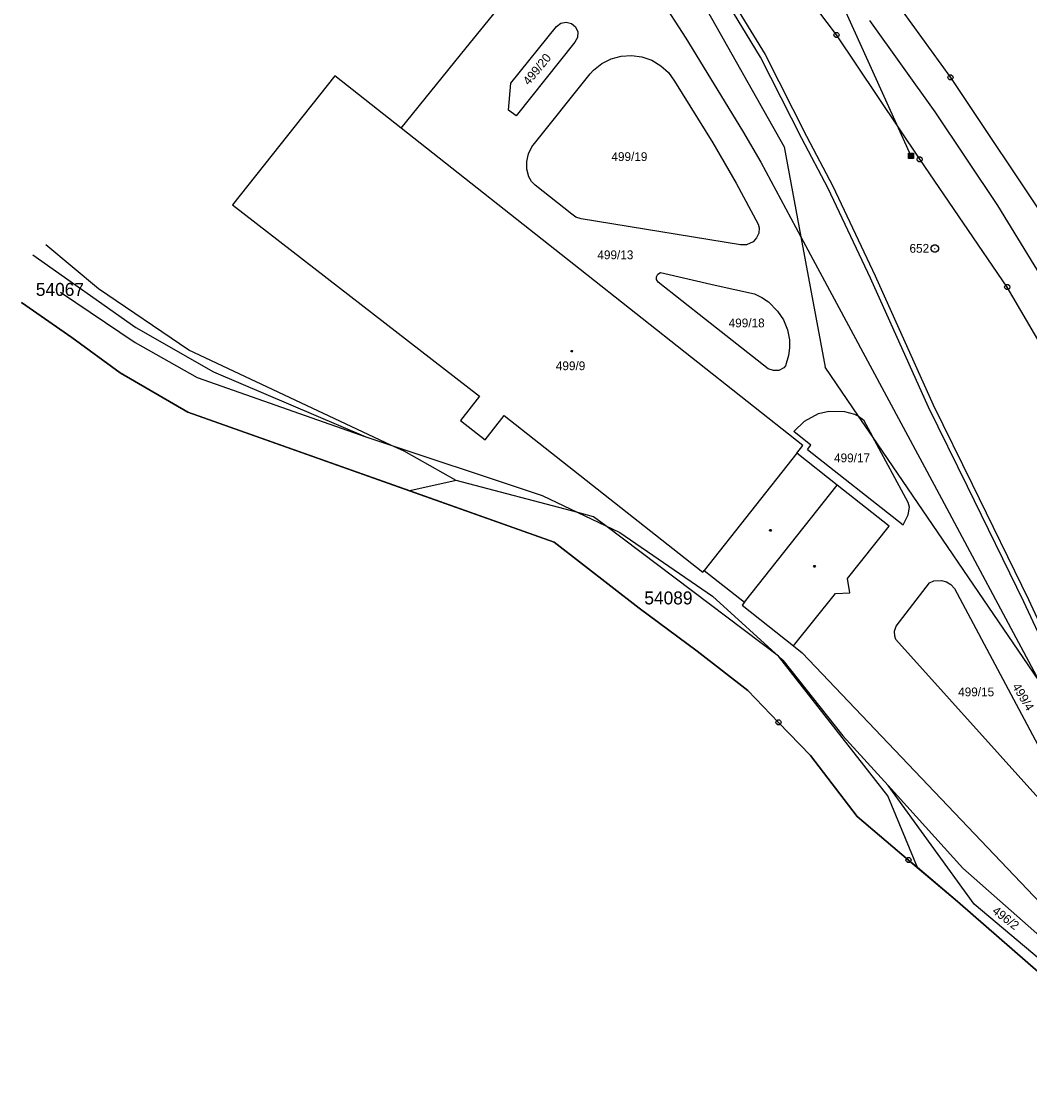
# Model space of a CAD drawing. Extents: x -755359 to -754474, y -1162585 to -1161655.
# Drawn here: x -755359.1 to -755164.4, y -1162482.8 to -1162276.2 of the extents above; entities that cross this region are included whole.
import ezdxf

# ---------------------------------------------------------------- set-up
doc = ezdxf.new("R2010")
doc.units = 0
for name, color, linetype in [('Vrstva 1', 7, 'Continuous'), ('Vrstva 11', 7, 'Continuous'), ('Vrstva 12', 7, 'Continuous'), ('Vrstva 13', 7, 'Continuous'), ('Vrstva 2', 7, 'Continuous'), ('Vrstva 4', 7, 'Continuous'), ('Vrstva 5', 7, 'Continuous'), ('Vrstva 6', 7, 'Continuous'), ('Vrstva 7', 7, 'Continuous'), ('Vrstva 8', 7, 'Continuous')]:
    doc.layers.add(name, color=color, linetype=linetype)

msp = doc.modelspace()

# ---------------------------------------------------------------- linework, layer by layer
at = {"layer": 'Vrstva 1'}
for p, q in [((-755201.65, -1162278.82), (-755218.86, -1162255.78)), ((-755197.95, -1162261.69), (-755179.66, -1162287.01)), ((-755273.15, -1162281.3), (-755259.96, -1162264.99)), ((-755228.92, -1162270), (-755211.8, -1162300.42)), ((-755236.16, -1162271.02), (-755230.79, -1162279.46)), ((-755255.71, -1162277.19), (-755254.89, -1162276.55)), ((-755254.89, -1162276.55), (-755253.87, -1162276.34)), ((-755253.87, -1162276.34), (-755252.85, -1162276.59)), ((-755252.85, -1162276.59), (-755252.05, -1162277.27)), ((-755264.53, -1162288.11), (-755255.71, -1162277.19)), ((-755252.05, -1162277.27), (-755251.62, -1162278.23)), ((-755251.62, -1162278.23), (-755251.7, -1162279.29)), ((-755252.21, -1162280.19), (-755263.5, -1162294.45)), ((-755251.7, -1162279.29), (-755252.21, -1162280.19)), ((-755230.79, -1162279.46), (-755219.8, -1162297.35)), ((-755185.6, -1162302.84), (-755201.65, -1162278.82)), ((-755285.72, -1162296.84), (-755273.15, -1162281.3)), ((-755245.19, -1162283.44), (-755243.24, -1162282.9)), ((-755243.24, -1162282.9), (-755241.22, -1162282.77)), ((-755241.22, -1162282.77), (-755239.23, -1162283.04)), ((-755248.56, -1162285.61), (-755246.99, -1162284.35)), ((-755246.99, -1162284.35), (-755245.19, -1162283.44)), ((-755239.23, -1162283.04), (-755237.32, -1162283.7)), ((-755237.32, -1162283.7), (-755235.58, -1162284.76)), ((-755235.58, -1162284.76), (-755234.1, -1162286.1)), ((-755298.53, -1162286.71), (-755318.27, -1162311.63)), ((-755285.72, -1162296.84), (-755298.53, -1162286.71)), ((-755260.47, -1162300.43), (-755249.26, -1162286.35)), ((-755249.26, -1162286.35), (-755248.56, -1162285.61)), ((-755234.1, -1162286.1), (-755232.92, -1162287.74)), ((-755179.66, -1162287.01), (-755159.89, -1162316.68)), ((-755265.01, -1162293.32), (-755264.53, -1162288.11)), ((-755232.92, -1162287.74), (-755225.57, -1162299.65)), ((-755263.5, -1162294.45), (-755265.01, -1162293.32)), ((-755251.18, -1162324.13), (-755285.72, -1162296.84)), ((-755219.8, -1162297.35), (-755216.28, -1162303.42)), ((-755261.16, -1162301.78), (-755260.47, -1162300.43)), ((-755225.57, -1162299.65), (-755221.06, -1162307.45)), ((-755211.8, -1162300.42), (-755208.54, -1162317.82)), ((-755261.48, -1162303.26), (-755261.16, -1162301.78)), ((-755261.47, -1162304.77), (-755261.48, -1162303.26)), ((-755216.28, -1162303.42), (-755208.54, -1162317.82)), ((-755168.69, -1162327.53), (-755185.6, -1162302.84)), ((-755261.1, -1162306.25), (-755261.47, -1162304.77)), ((-755260.58, -1162307.15), (-755261.1, -1162306.25)), ((-755259.87, -1162307.84), (-755260.58, -1162307.15)), ((-755221.06, -1162307.45), (-755216.79, -1162315.38)), ((-755252.8, -1162313.43), (-755259.87, -1162307.84)), ((-755318.27, -1162311.63), (-755270.6, -1162348.62)), ((-755251.97, -1162314.01), (-755252.8, -1162313.43)), ((-755250.99, -1162314.33), (-755251.97, -1162314.01)), ((-755220.22, -1162319.37), (-755250.99, -1162314.33)), ((-755216.79, -1162315.38), (-755216.6, -1162316.07)), ((-755217.09, -1162318.02), (-755217.77, -1162318.78)), ((-755216.69, -1162317.09), (-755217.09, -1162318.02)), ((-755216.6, -1162316.07), (-755216.69, -1162317.09)), ((-755208.54, -1162317.82), (-755203.83, -1162343)), ((-755219.05, -1162319.34), (-755220.22, -1162319.37)), ((-755217.77, -1162318.78), (-755219.05, -1162319.34)), ((-755356.88, -1162321.27), (-755356.88, -1162321.27)), ((-755356.88, -1162321.27), (-755336.95, -1162335.3)), ((-755208.16, -1162358.13), (-755251.18, -1162324.13)), ((-755236.45, -1162325.52), (-755236.16, -1162325.01)), ((-755236.44, -1162326.06), (-755236.45, -1162325.52)), ((-755236.12, -1162326.55), (-755236.44, -1162326.06)), ((-755236.16, -1162325.01), (-755235.64, -1162324.73)), ((-755235.64, -1162324.73), (-755225.07, -1162327.13)), ((-755226.97, -1162333.77), (-755236.12, -1162326.55)), ((-755225.07, -1162327.13), (-755217.5, -1162328.85)), ((-755155.26, -1162350.62), (-755168.69, -1162327.53)), ((-755351.54, -1162328.52), (-755351.54, -1162328.52)), ((-755351.54, -1162328.52), (-755337.08, -1162338.23)), ((-755217.5, -1162328.85), (-755216.09, -1162329.51)), ((-755216.09, -1162329.51), (-755214.81, -1162330.37)), ((-755214.81, -1162330.37), (-755213.06, -1162332.17)), ((-755359.06, -1162330.53), (-755359.06, -1162330.53)), ((-755359.06, -1162330.53), (-755349.35, -1162337.24)), ((-755213.06, -1162332.17), (-755211.93, -1162333.85)), ((-755214.89, -1162343.31), (-755226.97, -1162333.77)), ((-755211.93, -1162333.85), (-755211.16, -1162335.75)), ((-755336.95, -1162335.3), (-755321.94, -1162343.88)), ((-755211.16, -1162335.75), (-755210.72, -1162337.72)), ((-755349.35, -1162337.24), (-755339.99, -1162344.07)), ((-755337.08, -1162338.23), (-755325.14, -1162344.97)), ((-755210.72, -1162337.72), (-755210.71, -1162339.28)), ((-755210.71, -1162339.28), (-755210.94, -1162340.77)), ((-755211.5, -1162342.72), (-755211.86, -1162343.11)), ((-755210.94, -1162340.77), (-755211.5, -1162342.72)), ((-755339.99, -1162344.07), (-755326.91, -1162351.67)), ((-755321.94, -1162343.88), (-755292.52, -1162356.43)), ((-755213.83, -1162343.62), (-755214.89, -1162343.31)), ((-755212.81, -1162343.61), (-755213.83, -1162343.62)), ((-755211.86, -1162343.11), (-755212.81, -1162343.61)), ((-755197.4, -1162352.43), (-755203.83, -1162343)), ((-755325.14, -1162344.97), (-755292.52, -1162356.43)), ((-755270.6, -1162348.62), (-755274.29, -1162353.28)), ((-755326.91, -1162351.67), (-755256.17, -1162376.79)), ((-755269.5, -1162357.01), (-755265.84, -1162352.32)), ((-755265.84, -1162352.32), (-755227.45, -1162382.59)), ((-755207.82, -1162353.4), (-755205.14, -1162351.97)), ((-755205.14, -1162351.97), (-755203.16, -1162351.5)), ((-755203.16, -1162351.5), (-755200.13, -1162351.55)), ((-755200.13, -1162351.55), (-755198.17, -1162352.07)), ((-755198.17, -1162352.07), (-755197.4, -1162352.43)), ((-755194.7, -1162356.4), (-755197.4, -1162352.43)), ((-755274.29, -1162353.28), (-755269.5, -1162357.01)), ((-755209.93, -1162355.45), (-755207.82, -1162353.4)), ((-755292.52, -1162356.43), (-755258.5, -1162367.8)), ((-755206.63, -1162358.07), (-755209.93, -1162355.45)), ((-755187.86, -1162369.11), (-755194.7, -1162356.4)), ((-755162.59, -1162403.5), (-755194.7, -1162356.4)), ((-755209.34, -1162359.63), (-755208.16, -1162358.13)), ((-755207.28, -1162358.88), (-755206.63, -1162358.07)), ((-755207.28, -1162358.88), (-755188.78, -1162373.43)), ((-755201.54, -1162365.82), (-755209.34, -1162359.63)), ((-755191.47, -1162373.73), (-755201.54, -1162365.82)), ((-755258.5, -1162367.8), (-755243.5, -1162374.93)), ((-755187.6, -1162370.02), (-755187.86, -1162369.11)), ((-755188.78, -1162373.43), (-755187.8, -1162371.5)), ((-755187.8, -1162371.5), (-755187.6, -1162370.02)), ((-755199.54, -1162383.8), (-755191.47, -1162373.73)), ((-755243.5, -1162374.93), (-755225.6, -1162387.24)), ((-755256.17, -1162376.79), (-755239.79, -1162389.54)), ((-755227.45, -1162382.59), (-755227.22, -1162382.29)), ((-755227.22, -1162382.29), (-755219.41, -1162388.42)), ((-755199.09, -1162386.57), (-755199.54, -1162383.8)), ((-755190.17, -1162393.03), (-755183.69, -1162384.68)), ((-755183.69, -1162384.68), (-755182.85, -1162384.3)), ((-755182.85, -1162384.3), (-755181.4, -1162384.23)), ((-755181.4, -1162384.23), (-755180.44, -1162384.49)), ((-755180.44, -1162384.49), (-755179.57, -1162384.99)), ((-755179.57, -1162384.99), (-755178.91, -1162385.78)), ((-755178.91, -1162385.78), (-755157.62, -1162425.68)), ((-755225.6, -1162387.24), (-755212.01, -1162399.57)), ((-755209.95, -1162396.8), (-755201.89, -1162386.73)), ((-755201.89, -1162386.73), (-755199.09, -1162386.57)), ((-755239.79, -1162389.54), (-755228.6, -1162397.87)), ((-755219.41, -1162388.42), (-755219.88, -1162388.97)), ((-755219.88, -1162388.97), (-755209.95, -1162396.8)), ((-755190.46, -1162393.97), (-755190.17, -1162393.03)), ((-755190.43, -1162394.96), (-755190.46, -1162393.97)), ((-755190.23, -1162395.62), (-755190.43, -1162394.96)), ((-755158.19, -1162431.25), (-755190.23, -1162395.62)), ((-755228.6, -1162397.87), (-755218.77, -1162405.46)), ((-755209.95, -1162396.8), (-755208.3, -1162398.17)), ((-755208.3, -1162398.17), (-755155.2, -1162454)), ((-755212.01, -1162399.57), (-755200.43, -1162414.21)), ((-755218.77, -1162405.46), (-755212.85, -1162411.61)), ((-755212.85, -1162411.61), (-755206.7, -1162418)), ((-755200.43, -1162414.21), (-755191.72, -1162423.82)), ((-755206.7, -1162418), (-755197.66, -1162429.8)), ((-755175.06, -1162446.75), (-755191.72, -1162423.82)), ((-755191.72, -1162423.82), (-755177.29, -1162439.75)), ((-755197.66, -1162429.8), (-755187.75, -1162438.21)), ((-755187.75, -1162438.21), (-755178.31, -1162446.22)), ((-755177.29, -1162439.75), (-755147.93, -1162465.72)), ((-755178.31, -1162446.22), (-755136.42, -1162482.75)), ((-755139.64, -1162476.61), (-755175.06, -1162446.75))]:
    msp.add_line(p, q, dxfattribs=at)
at = {"layer": 'Vrstva 11'}
for p, q in [((-755344.14, -1162327.86), (-755354.32, -1162319.38)), ((-755326.74, -1162339.72), (-755344.14, -1162327.86)), ((-755349.35, -1162337.24), (-755359.06, -1162330.53)), ((-755339.99, -1162344.07), (-755349.35, -1162337.24)), ((-755287.71, -1162358.04), (-755326.74, -1162339.72)), ((-755326.91, -1162351.67), (-755339.99, -1162344.07)), ((-755284.05, -1162366.89), (-755326.91, -1162351.67)), ((-755285.17, -1162359.23), (-755287.71, -1162358.04)), ((-755275.1, -1162364.9), (-755285.17, -1162359.23)), ((-755275.1, -1162364.9), (-755284.05, -1162366.89)), ((-755251.62, -1162371.07), (-755275.1, -1162364.9)), ((-755256.17, -1162376.79), (-755284.05, -1162366.89)), ((-755248.56, -1162371.88), (-755251.62, -1162371.07)), ((-755246.23, -1162373.63), (-755248.56, -1162371.88)), ((-755212.86, -1162398.83), (-755246.23, -1162373.63)), ((-755239.79, -1162389.54), (-755256.17, -1162376.79)), ((-755228.6, -1162397.87), (-755239.79, -1162389.54)), ((-755218.77, -1162405.46), (-755228.6, -1162397.87)), ((-755191.73, -1162425.79), (-755212.86, -1162398.83)), ((-755212.85, -1162411.61), (-755218.77, -1162405.46)), ((-755206.7, -1162418), (-755212.85, -1162411.61)), ((-755197.66, -1162429.8), (-755206.7, -1162418)), ((-755186.05, -1162439.65), (-755191.73, -1162425.79)), ((-755187.75, -1162438.21), (-755197.66, -1162429.8)), ((-755186.05, -1162439.65), (-755187.75, -1162438.21)), ((-755178.31, -1162446.22), (-755186.05, -1162439.65)), ((-755136.42, -1162482.75), (-755178.31, -1162446.22))]:
    msp.add_line(p, q, dxfattribs=at)
at = {"layer": 'Vrstva 12'}
for p, q in [((-755298.53, -1162286.71), (-755318.27, -1162311.63)), ((-755285.72, -1162296.84), (-755298.53, -1162286.71)), ((-755251.18, -1162324.13), (-755285.72, -1162296.84)), ((-755318.27, -1162311.63), (-755270.6, -1162348.62)), ((-755208.16, -1162358.13), (-755251.18, -1162324.13)), ((-755270.6, -1162348.62), (-755274.29, -1162353.28)), ((-755269.5, -1162357.01), (-755265.84, -1162352.32)), ((-755265.84, -1162352.32), (-755227.45, -1162382.59)), ((-755274.29, -1162353.28), (-755269.5, -1162357.01)), ((-755209.34, -1162359.63), (-755208.16, -1162358.13)), ((-755209.34, -1162359.63), (-755227.22, -1162382.29)), ((-755227.45, -1162382.59), (-755227.22, -1162382.29))]:
    msp.add_line(p, q, dxfattribs=at)
at = {"layer": 'Vrstva 13'}
for p, q in [((-755216.34, -1162283.1), (-755226.08, -1162267.13)), ((-755225.24, -1162266.57), (-755215.46, -1162282.62)), ((-755215.46, -1162282.62), (-755207.47, -1162298.36)), ((-755208.35, -1162298.82), (-755216.34, -1162283.1)), ((-755203.29, -1162308.45), (-755208.35, -1162298.82)), ((-755207.47, -1162298.36), (-755202.39, -1162308.01)), ((-755195.12, -1162325.8), (-755203.29, -1162308.45)), ((-755202.39, -1162308.01), (-755194.22, -1162325.38)), ((-755183.93, -1162350.73), (-755195.12, -1162325.8)), ((-755194.22, -1162325.38), (-755183.03, -1162350.29)), ((-755176.37, -1162366.06), (-755183.93, -1162350.73)), ((-755183.03, -1162350.29), (-755175.47, -1162365.62)), ((-755165.49, -1162388.31), (-755176.37, -1162366.06)), ((-755175.47, -1162365.62), (-755164.59, -1162387.87)), ((-755164.59, -1162387.87), (-755160.04, -1162397.7)), ((-755160.94, -1162398.14), (-755165.49, -1162388.31))]:
    msp.add_line(p, q, dxfattribs=at)
at = {"layer": 'Vrstva 4'}
for p, q in [((-755208.54, -1162317.82), (-755182.37, -1162366.53)), ((-755197.4, -1162352.43), (-755196.45, -1162353.14)), ((-755196.45, -1162353.14), (-755194.7, -1162356.4)), ((-755209.34, -1162359.63), (-755227.22, -1162382.29)), ((-755219.41, -1162388.42), (-755201.54, -1162365.82)), ((-755182.37, -1162366.53), (-755162.59, -1162403.5))]:
    msp.add_line(p, q, dxfattribs=at)
at = {"layer": 'Vrstva 5'}
for points in [[(-755252.7, -1162339.75), (-755252.61, -1162339.9), (-755252.7, -1162340.05), (-755252.88, -1162340.05), (-755252.97, -1162339.9), (-755252.88, -1162339.75)], [(-755214.33, -1162374.35), (-755214.24, -1162374.5), (-755214.33, -1162374.65), (-755214.51, -1162374.65), (-755214.6, -1162374.5), (-755214.51, -1162374.35)], [(-755205.82, -1162381.32), (-755205.73, -1162381.47), (-755205.82, -1162381.62), (-755206, -1162381.62), (-755206.09, -1162381.47), (-755206, -1162381.32)]]:
    msp.add_lwpolyline(points, close=True, dxfattribs=at)
at = {"layer": 'Vrstva 6'}
for p, q in [((-755245.56, -1162173.47), (-755187.29, -1162302.18)), ((-755195.32, -1162276.05), (-755182.68, -1162293.67)), ((-755182.68, -1162293.67), (-755170.6, -1162311.78)), ((-755170.6, -1162311.78), (-755159.25, -1162330.3))]:
    msp.add_line(p, q, dxfattribs=at)
msp.add_lwpolyline([(-755187.79, -1162301.68), (-755186.79, -1162301.68), (-755186.79, -1162302.68), (-755187.79, -1162302.68), (-755187.79, -1162301.68), (-755187.73, -1162301.74), (-755186.85, -1162301.74), (-755186.85, -1162301.82), (-755187.73, -1162301.82), (-755187.73, -1162301.9), (-755186.85, -1162301.9), (-755186.85, -1162301.98), (-755187.73, -1162301.98), (-755187.73, -1162302.06), (-755186.85, -1162302.06), (-755186.85, -1162302.14), (-755187.73, -1162302.14), (-755187.73, -1162302.22), (-755186.85, -1162302.22), (-755186.85, -1162302.3), (-755187.73, -1162302.3), (-755187.73, -1162302.38), (-755186.85, -1162302.38), (-755186.85, -1162302.46), (-755187.73, -1162302.46), (-755187.73, -1162302.54), (-755186.85, -1162302.54), (-755186.85, -1162302.62), (-755187.73, -1162302.62)], dxfattribs=at)
at = {"layer": 'Vrstva 8'}
for p, q in [((-755201.77, -1162278.82), (-755201.53, -1162278.82)), ((-755179.78, -1162287.01), (-755179.54, -1162287.01)), ((-755185.72, -1162302.84), (-755185.48, -1162302.84)), ((-755182.72, -1162320.06), (-755182.62, -1162320.06)), ((-755168.81, -1162327.53), (-755168.57, -1162327.53)), ((-755212.97, -1162411.61), (-755212.73, -1162411.61)), ((-755187.87, -1162438.21), (-755187.63, -1162438.21))]:
    msp.add_line(p, q, dxfattribs=at)
for points in [[(-755201.5, -1162278.34), (-755201.25, -1162278.52), (-755201.15, -1162278.81), (-755201.25, -1162279.1), (-755201.5, -1162279.28), (-755201.81, -1162279.28), (-755202.06, -1162279.1), (-755202.16, -1162278.81), (-755202.06, -1162278.52), (-755201.81, -1162278.34)], [(-755179.51, -1162286.53), (-755179.26, -1162286.71), (-755179.16, -1162287), (-755179.26, -1162287.29), (-755179.51, -1162287.47), (-755179.82, -1162287.47), (-755180.07, -1162287.29), (-755180.17, -1162287), (-755180.07, -1162286.71), (-755179.82, -1162286.53)], [(-755185.45, -1162302.36), (-755185.2, -1162302.54), (-755185.1, -1162302.83), (-755185.2, -1162303.12), (-755185.45, -1162303.3), (-755185.76, -1162303.3), (-755186.01, -1162303.12), (-755186.11, -1162302.83), (-755186.01, -1162302.54), (-755185.76, -1162302.36)], [(-755182.48, -1162319.34), (-755182.14, -1162319.53), (-755181.95, -1162319.87), (-755181.95, -1162320.26), (-755182.14, -1162320.6), (-755182.48, -1162320.79), (-755182.87, -1162320.79), (-755183.21, -1162320.6), (-755183.4, -1162320.26), (-755183.4, -1162319.87), (-755183.21, -1162319.53), (-755182.87, -1162319.34)], [(-755168.54, -1162327.05), (-755168.29, -1162327.23), (-755168.19, -1162327.52), (-755168.29, -1162327.81), (-755168.54, -1162327.99), (-755168.85, -1162327.99), (-755169.1, -1162327.81), (-755169.2, -1162327.52), (-755169.1, -1162327.23), (-755168.85, -1162327.05)], [(-755212.7, -1162411.13), (-755212.45, -1162411.31), (-755212.35, -1162411.6), (-755212.45, -1162411.89), (-755212.7, -1162412.07), (-755213.01, -1162412.07), (-755213.26, -1162411.89), (-755213.36, -1162411.6), (-755213.26, -1162411.31), (-755213.01, -1162411.13)], [(-755187.6, -1162437.73), (-755187.35, -1162437.91), (-755187.25, -1162438.2), (-755187.35, -1162438.49), (-755187.6, -1162438.67), (-755187.91, -1162438.67), (-755188.16, -1162438.49), (-755188.26, -1162438.2), (-755188.16, -1162437.91), (-755187.91, -1162437.73)]]:
    msp.add_lwpolyline(points, close=True, dxfattribs=at)

# ---------------------------------------------------------------- texts
at = {"layer": 'Vrstva 11'}
for s, p in [('54067', (-755356.271, -1162329.22)), ('54089', (-755238.77, -1162388.82))]:
    msp.add_text(s, height=2.5, dxfattribs=at).set_placement(p)
at = {"layer": 'Vrstva 2'}
for s, rotation, p in [('499/20', 50.36299, (-755261.074, -1162288.652)), ('496/2', 322.17417, (-755171.742, -1162448.326))]:
    msp.add_text(s, height=1.7, rotation=rotation, dxfattribs=at).set_placement(p)
for s, p in [('499/19', (-755245.134, -1162303.17)), ('499/13', (-755247.841, -1162322.14)), ('499/18', (-755222.494, -1162335.3)), ('499/9', (-755255.863, -1162343.58)), ('499/17', (-755202.144, -1162361.37)), ('499/15', (-755178.181, -1162406.58))]:
    msp.add_text(s, height=1.7, dxfattribs=at).set_placement(p)
at = {"layer": 'Vrstva 7'}
msp.add_text('499/4', height=1.7, rotation=300.97473, dxfattribs=at).set_placement((-755167.806, -1162404.679))
at = {"layer": 'Vrstva 8'}
msp.add_text('652', height=1.7, dxfattribs=at).set_placement((-755187.573, -1162320.89))

doc.saveas('drawing.dxf')
